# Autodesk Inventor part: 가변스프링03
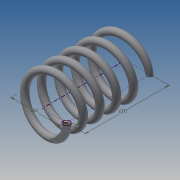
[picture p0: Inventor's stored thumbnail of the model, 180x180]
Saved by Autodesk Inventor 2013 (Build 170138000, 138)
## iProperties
Created: 2014-07
Part Number: 가변스프링03
Material: 일반
Document SubType Name: Modeling
Designer: SEMTLE01_MAIN
Density: 1 g/cm^3
Author: SEMTLE01_MAIN
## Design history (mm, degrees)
sketch "스케치1"
  geometry: L1 (0, 0)-(11, 0); L2 (11, 0)-(11, 36.411); L3 (11, 36.411)-(0, 36.411); L4 (0, 36.411)-(0, 0); C1 r 1.5 at (11, 0)
  constraints: 8 end point, 2 parallel, 1 centre point, 1 coincident, 1 horizontal, 1 perpendicular
  dimensions: "d0" = 3 diameter of C1; "d2" = 22 diameter of L1.end L4; "d3" = 36.4112 distance of L1.end L2.end (derived)
feature "코일1" pitch "d4" = 10; turns "d6" = 5; dims "d5" = 36.4112 (= d3), "d7" = 0, angle "d8" = 90 deg, angle "d9" = 90 deg, "d10" = 0, "d11" = 0
sketch "스케치2"
  geometry: L1 (-12.5, 0)-(-9.5, 0) reference; 1 further point
  constraints: 1 horizontal alignment
extrude "돌출1" cut sketch "스케치2" stored distance "d12" = 10; taper "d13" = 0 deg
node "작업 평면1"
sketch "스케치3"
  geometry: L1 (1.5, 0)-(-1.5, 0) reference; 1 further point
  constraints: 1 horizontal alignment
extrude "돌출2" cut sketch "스케치3" stored distance "d15" = 10; taper "d16" = 0 deg
node "솔리드1"
node "절단 모서리 투영1"
node "절단 모서리 투영2"
other parameters: "d14" = 0
